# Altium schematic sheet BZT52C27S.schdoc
size 127 x 101 mm
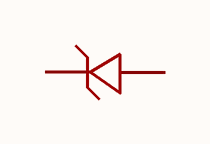
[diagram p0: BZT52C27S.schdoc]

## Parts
ZD?  bzt52c27s_c22621  [SOD-323_L1.8-W1.3-LS2.5-RD]  (value not drawn)

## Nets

Not connected (* = marked no-connect by the designer): ZD? 1(K) 2(A)

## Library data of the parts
ZD? = bzt52c27s_c22621: 二极管配置:1个独立式;稳压值(标称值):27V;稳压值(范围值):25.1V~28.9V;耗散功率(Pd):200mW;; Manufacturer: CJ(江苏长电/长晶); AddInBom: yes; ModelId: db63db13d9e342eb939127d413d6200b; ModelTransform: 104.3305,51.181,0,0,0,0,0,-0.004,0; Diode Configuration: 1个独立式; Zener Voltage(Nom): 27V; Reverse Leakage Current (Ir): 100nA; Pd - Power Dissipation: 200mW; Impedance(Zzt): 80Ω; Impedance(Zzk): 300Ω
